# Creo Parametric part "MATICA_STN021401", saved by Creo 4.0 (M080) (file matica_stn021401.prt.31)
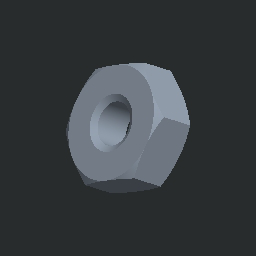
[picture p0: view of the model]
Units: Custom; MM, KILOGRAM, SECS
Materials in the file: OCEL_N

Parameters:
  MFG_WP_MATERIAL = "OCEL"
  NAZOV = "MATICA_STN021401"
  NORMA = "STN 02 1401"
  PTC_MATERIAL_NAME = "OCEL_N"

Other parameters: HMOTNOST, HUSTOTA, D12, D19

Created from: C021401.PRT

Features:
  1. datum plane "DTM1"
  2. cut
  3. cut
  4. datum plane "DTM2"
  5. datum plane "DTM3"

Other named items: THRU

Layers: 1, 2, 3, 4, 5, 6, 7, 8, 9, 10, 11, 12, 13, 14, 15, 16, 17, 18, 19, 20, 21, 22, 23, 24, 25, 26, 27, 28, 29, 30, 31, 32, ROVINY

Family table entries: GENERIC, MATICA_M1_6, MATICA_STN021401, value(d_val), value(i_val), MATICA_M2, MATICA_STN021401, MATICA_M2_5, MATICA_STN021401, MATICA_M3, MATICA_STN021401, MATICA_M4, MATICA_STN021401, MATICA_M5, MATICA_STN021401, 2/ , MATICA_M6, MATICA_STN021401, 2/$, MATICA_M8, MATICA_STN021401, !/ , 2/*, MATICA_M8X1, MATICA_STN021401, !/ , 2/*, MATICA_M10, MATICA_STN021401, !/$, 2/ , 2/0, MATICA_M10X1_25, MATICA_STN021401, !/$, 2/ , 2/0, MATICA_M12, MATICA_STN021401, !/(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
